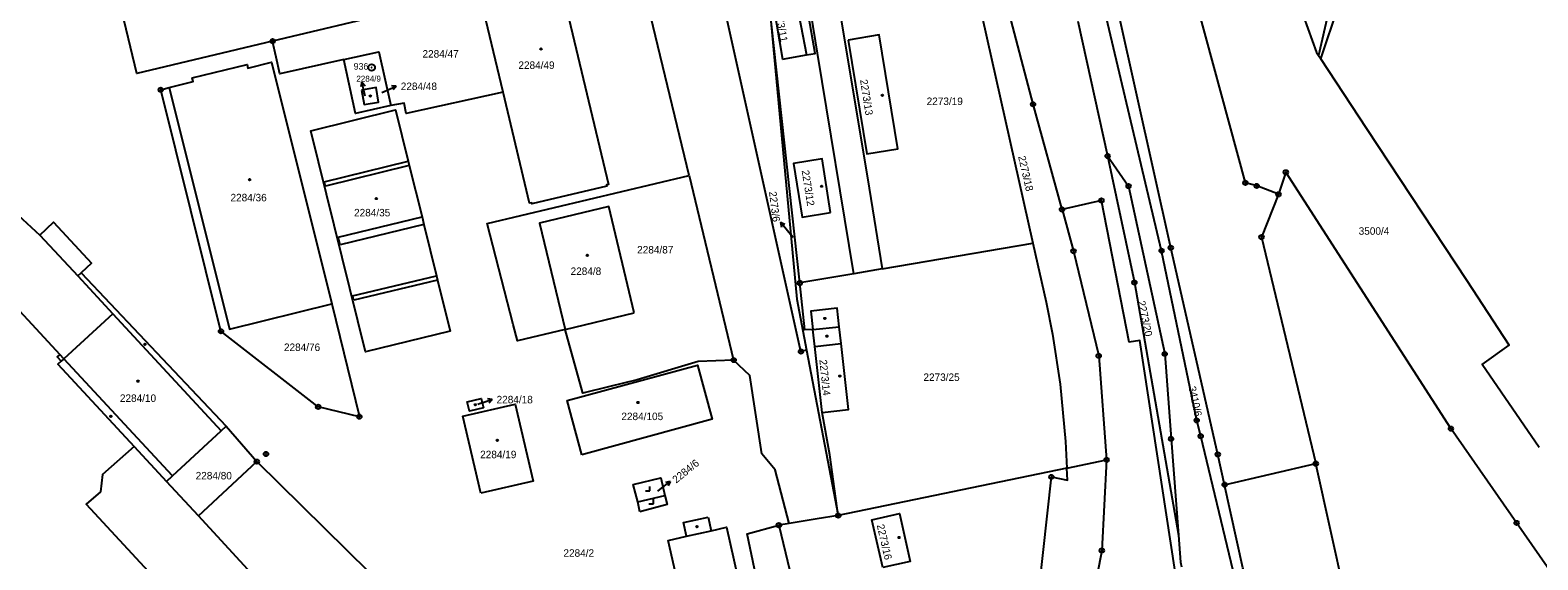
# Model space of a CAD drawing. Extents: x -733394 to -722299, y -1082822 to -1075049.
# Drawn here: x -728924.3 to -728582.2, y -1080231.7 to -1080111.4 of the extents above; entities that cross this region are included whole.
import ezdxf

# ---------------------------------------------------------------- set-up
doc = ezdxf.new("R2010")
doc.units = 0
for name, color, linetype in [('Hranice parcel', 7, 'Continuous'), ('Parcelní čísla', 7, 'Continuous'), ('Pop  PČ popisy', 7, 'Continuous'), ('Vnitřní kresba', 7, 'Continuous'), ('Značky bodu BP', 7, 'Continuous'), ('Značky budov', 7, 'Continuous'), ('Značky kultur', 7, 'Continuous')]:
    doc.layers.add(name, color=color, linetype=linetype)

msp = doc.modelspace()

# ---------------------------------------------------------------- linework, layer by layer
at = {"layer": 'Hranice parcel'}
for p, q in [((-728774.79, -1080144.43), (-728789.19, -1080084.77)), ((-728711.6, -1080093.48), (-728696.79, -1080159.78)), ((-728817.02, -1080125.51), (-728822.46, -1080102.76)), ((-728749.67, -1080168.84), (-728756.71, -1080104.45)), ((-728841.26, -1080107.25), (-728869.31, -1080113.95)), ((-728686.59, -1080109.41), (-728679.82, -1080140.01)), ((-728631.97, -1080117.2), (-728631.45, -1080117.98)), ((-728774.79, -1080144.43), (-728764.68, -1080186.34)), ((-728730.95, -1080165.63), (-728696.79, -1080159.78)), ((-728730.95, -1080165.63), (-728737.42, -1080166.74)), ((-728737.42, -1080166.74), (-728749.67, -1080168.84)), ((-728748.16, -1080184.12), (-728740.95, -1080221.65)), ((-728879.85, -1080201.33), (-728872.89, -1080209.38)), ((-728900.7, -1080205.97), (-728893.37, -1080213.87)), ((-728886.17, -1080221.68), (-728872.89, -1080209.38)), ((-728689.04, -1080210.85), (-728740.95, -1080221.65)), ((-728689.04, -1080210.85), (-728680.04, -1080208.98)), ((-728653.27, -1080214.63), (-728632.56, -1080209.85)), ((-728886.17, -1080221.68), (-728893.37, -1080213.87)), ((-728848.41, -1080262.69), (-728886.17, -1080221.68)), ((-728752.11, -1080223.45), (-728754.43, -1080223.82))]:
    msp.add_line(p, q, dxfattribs=at)
for points in [[(-728737.42, -1080166.74), (-728745.68, -1080116.63), (-728765.96, -1079991.74)], [(-728748.16, -1080184.12), (-728749.41, -1080184.4), (-728775.59, -1080066.46), (-728782.41, -1080049.95), (-728783.38, -1080044.86), (-728786.24, -1080022.54)], [(-728641.02, -1080148.71), (-728645.96, -1080146.81), (-728648.54, -1080146.1), (-728661.28, -1080098.98), (-728659.63, -1080032.24)], [(-728631.45, -1080117.98), (-728627.39, -1080106), (-728622.27, -1080086.64), (-728619.99, -1080056.5), (-728617.8, -1080049.81), (-728606.86, -1080033.11)], [(-728619.68, -1080042.48), (-728623.49, -1080050.29), (-728626.58, -1080093.66), (-728631.97, -1080117.2)], [(-728653.27, -1080214.63), (-728654.79, -1080207.75), (-728665.47, -1080160.84), (-728681.06, -1080090.76), (-728699.52, -1080051.66)], [(-728690.16, -1080152.15), (-728696.72, -1080128.27), (-728707.84, -1080085.86), (-728715.83, -1080054.04)], [(-728630.66, -1080308.05), (-728651.31, -1080234.15), (-728658.68, -1080203.61), (-728659.58, -1080200.04), (-728667.56, -1080161.51), (-728684.06, -1080091.71), (-728696.41, -1080065.56)], [(-728807.03, -1080088.14), (-728793.08, -1080146.46), (-728793.56, -1080146.58), (-728793.5, -1080146.84), (-728810.45, -1080150.87), (-728810.49, -1080150.63), (-728810.98, -1080150.74), (-728817.02, -1080125.51)], [(-728869.31, -1080113.95), (-728900.14, -1080121.31), (-728903.96, -1080105.23), (-728874.06, -1080098.09)], [(-728753.56, -1080118), (-728748.14, -1080117.08), (-728746.17, -1080116.72), (-728748.96, -1080100.62), (-728751.24, -1080100.94), (-728756.35, -1080101.9), (-728753.56, -1080118)], [(-728741.87, -1080099.63), (-728740.52, -1080107.73), (-728733.91, -1080147.32), (-728730.95, -1080165.63)], [(-728756.71, -1080104.45), (-728750.38, -1080172.55), (-728748.16, -1080184.12)], [(-728635.36, -1080108.35), (-728632.43, -1080116.5), (-728631.97, -1080117.2)], [(-728853.13, -1080118.13), (-728867.64, -1080121.39), (-728868.5, -1080117.54), (-728869.31, -1080113.95)], [(-728738.72, -1080113.71), (-728734.49, -1080139.52), (-728727.42, -1080138.36), (-728731.65, -1080112.51), (-728738.72, -1080113.71)], [(-728853.13, -1080118.13), (-728845.22, -1080116.36), (-728842.47, -1080128.52)], [(-728842.47, -1080128.52), (-728850.47, -1080130.33), (-728853.13, -1080118.13)], [(-728581.87, -1080206.22), (-728594.79, -1080187.37), (-728588.7, -1080182.93), (-728598.19, -1080168.32), (-728620.98, -1080133.87), (-728631.45, -1080117.98)], [(-728892.77, -1080124.48), (-728887.35, -1080123.13), (-728887.57, -1080122.26), (-728875.12, -1080119.22), (-728874.91, -1080120.04), (-728869.54, -1080118.71), (-728855.9, -1080173.6)], [(-728855.9, -1080173.6), (-728849.62, -1080199.19), (-728858.97, -1080196.96), (-728881.03, -1080179.79), (-728894.71, -1080124.98), (-728892.77, -1080124.48)], [(-728892.77, -1080124.48), (-728879.09, -1080179.36), (-728855.9, -1080173.6)], [(-728849.12, -1080125.08), (-728848.54, -1080128.34), (-728845.27, -1080127.76), (-728845.83, -1080124.49), (-728849.12, -1080125.08)], [(-728817.02, -1080125.51), (-728838.97, -1080130.35), (-728839.49, -1080127.98), (-728842.47, -1080128.52)], [(-728834.98, -1080155.58), (-728832.11, -1080167.19), (-728831.87, -1080168.17), (-728829.01, -1080179.74), (-728848.2, -1080184.44), (-728860.67, -1080134.27), (-728841.42, -1080129.52), (-728838.53, -1080141.19), (-728838.29, -1080142.19), (-728835.41, -1080153.83), (-728834.98, -1080155.58)], [(-728944.46, -1080135.06), (-728929.01, -1080151.66), (-728922.12, -1080158)], [(-728742.67, -1080152.8), (-728744.6, -1080140.69), (-728751.1, -1080141.74), (-728749.15, -1080153.86), (-728742.67, -1080152.8)], [(-728679.82, -1080140.01), (-728673.74, -1080168.73), (-728663.75, -1080226.11)], [(-728679.82, -1080140.01), (-728675.06, -1080146.83), (-728666.85, -1080184.94), (-728665.41, -1080204.23), (-728663.75, -1080226.11)], [(-728955.63, -1080145.36), (-728940.22, -1080162.17), (-728933.21, -1080168.29), (-728917.64, -1080185.07)], [(-728764.68, -1080186.34), (-728772.77, -1080186.7), (-728786.55, -1080190.85), (-728792.8, -1080192.35), (-728798.9, -1080193.85), (-728802.92, -1080179.37), (-728813.75, -1080181.95), (-728814.69, -1080178.29), (-728820.59, -1080155.33), (-728774.79, -1080144.43)], [(-728553.39, -1080273.16), (-728558.52, -1080265.52), (-728573.03, -1080243.99), (-728574.8, -1080240.8), (-728586.99, -1080223.3), (-728601.9, -1080201.91), (-728639.36, -1080143.69), (-728641.02, -1080148.71)], [(-728641.02, -1080148.71), (-728644.89, -1080158.41), (-728632.56, -1080209.85)], [(-728787.24, -1080175.59), (-728793.04, -1080151.45), (-728808.74, -1080155.25), (-728802.92, -1080179.37), (-728787.24, -1080175.59)], [(-728663.81, -1080237.2), (-728664.51, -1080234.33), (-728672.47, -1080181.92), (-728674.93, -1080182.25), (-728681.21, -1080150.12), (-728690.16, -1080152.15)], [(-728690.16, -1080152.15), (-728687.56, -1080161.6), (-728681.84, -1080185.38), (-728680.04, -1080208.98)], [(-728922.12, -1080158), (-728919.02, -1080155.05), (-728910.41, -1080164.35), (-728912.73, -1080166.5), (-728879.85, -1080201.33)], [(-728922.12, -1080158), (-728913.54, -1080167.25), (-728905.59, -1080175.83), (-728916.71, -1080186.06), (-728917.64, -1080185.07)], [(-728696.79, -1080159.78), (-728693.78, -1080173.23), (-728692.29, -1080180.44), (-728690.56, -1080191.84), (-728689.37, -1080204.79), (-728689.04, -1080210.85)], [(-728746.7, -1080179.43), (-728748.5, -1080179.49), (-728749.67, -1080168.84)], [(-728744.62, -1080198.22), (-728738.62, -1080197.56), (-728740.28, -1080182.59), (-728740.71, -1080178.77), (-728741.17, -1080174.56), (-728747.17, -1080175.22), (-728746.7, -1080179.43)], [(-728744.62, -1080198.22), (-728746.28, -1080183.25), (-728746.7, -1080179.43)], [(-728917.64, -1080185.07), (-728918.23, -1080185.61), (-728917.31, -1080186.6), (-728918.04, -1080187.29), (-728900.7, -1080205.97)], [(-728752.11, -1080223.45), (-728755.25, -1080211.25), (-728758.32, -1080207.61), (-728761, -1080189.81), (-728764.68, -1080186.34)], [(-728799.14, -1080207.84), (-728802.49, -1080195.51), (-728772.88, -1080187.48), (-728769.55, -1080199.75), (-728799.14, -1080207.84)], [(-728822.08, -1080216.58), (-728826.14, -1080199.04), (-728814.26, -1080196.34), (-728810.17, -1080213.83), (-728822.08, -1080216.58)], [(-728821.45, -1080197.21), (-728824.63, -1080197.95), (-728825.13, -1080195.79), (-728821.95, -1080195.06), (-728821.45, -1080197.21)], [(-728740.95, -1080221.65), (-728742.88, -1080207.86), (-728744.62, -1080198.22)], [(-728893.37, -1080213.87), (-728892.05, -1080212.64), (-728880.97, -1080202.37), (-728879.85, -1080201.33)], [(-728900.7, -1080205.97), (-728907.9, -1080212.32), (-728908.37, -1080216.28), (-728911.61, -1080219.04), (-728863.64, -1080270.92), (-728866.08, -1080273.13), (-728868.18, -1080273.17)], [(-728872.89, -1080209.38), (-728837.18, -1080244.57), (-728832.81, -1080248.41)], [(-728728.7, -1080396.49), (-728712.16, -1080321.77), (-728703.02, -1080284.2), (-728696.32, -1080247.23), (-728692.56, -1080212.86), (-728688.89, -1080213.62), (-728689.04, -1080210.85)], [(-728680.04, -1080208.98), (-728681.12, -1080229.58), (-728684.34, -1080246.5), (-728693.5, -1080292.91), (-728701.3, -1080331.89), (-728714.47, -1080392.88), (-728727.79, -1080444.04)], [(-728606.47, -1080327.62), (-728632.47, -1080210.23), (-728632.56, -1080209.85)], [(-728785.94, -1080220.76), (-728786.46, -1080218.55), (-728787.45, -1080214.55), (-728781.23, -1080213.11), (-728780.28, -1080217.07), (-728779.74, -1080219.13), (-728785.94, -1080220.76)], [(-728628.39, -1080307.72), (-728649.09, -1080233.53), (-728653.27, -1080214.63)], [(-728730.86, -1080233.44), (-728733.31, -1080222.6), (-728727.04, -1080221.19), (-728724.63, -1080232.03), (-728730.86, -1080233.44)], [(-728770.47, -1080221.98), (-728769.79, -1080225.08), (-728766.27, -1080224.28), (-728758.94, -1080256.97), (-728772.15, -1080259.96), (-728774.42, -1080249.88), (-728775.84, -1080243.58), (-728779.52, -1080227.27), (-728775.4, -1080226.34), (-728776.1, -1080223.25), (-728770.47, -1080221.98)], [(-728755.99, -1080252.53), (-728761.65, -1080225.76), (-728754.43, -1080223.82)], [(-728754.43, -1080223.82), (-728747.91, -1080250.82), (-728755.99, -1080252.53)], [(-728740.95, -1080221.65), (-728745.69, -1080222.41), (-728752.11, -1080223.45)], [(-728663.75, -1080226.11), (-728663.29, -1080232.22), (-728663.02, -1080233.3)]]:
    msp.add_lwpolyline(points, dxfattribs=at)
at = {"layer": 'Pop  PČ popisy'}
for p, q in [((-728849.05, -1080123.22), (-728849.31, -1080124.3)), ((-728848.37, -1080126.14), (-728849.05, -1080123.22)), ((-728849.05, -1080123.22), (-728848.33, -1080124.08)), ((-728844.55, -1080125.57), (-728844, -1080125.34)), ((-728844, -1080125.34), (-728841.24, -1080124.17)), ((-728841.24, -1080124.17), (-728842.35, -1080124.1)), ((-728841.24, -1080124.17), (-728841.96, -1080125.02)), ((-728848.3, -1080126.44), (-728848.37, -1080126.14)), ((-728752.13, -1080157.36), (-728754.06, -1080155.06)), ((-728754.06, -1080155.06), (-728753.03, -1080155.51)), ((-728754.06, -1080155.06), (-728753.8, -1080156.15)), ((-728751.16, -1080158.52), (-728752.13, -1080157.36)), ((-728822.76, -1080196.37), (-728822.33, -1080196.23)), ((-728822.33, -1080196.23), (-728819.48, -1080195.3)), ((-728819.48, -1080195.3), (-728820.58, -1080195.14)), ((-728819.48, -1080195.3), (-728820.27, -1080196.09)), ((-728781.45, -1080215.75), (-728779.09, -1080213.9)), ((-728779.09, -1080213.9), (-728780.18, -1080214.12)), ((-728779.09, -1080213.9), (-728779.57, -1080214.91)), ((-728781.9, -1080216.1), (-728781.45, -1080215.75))]:
    msp.add_line(p, q, dxfattribs=at)
at = {"layer": 'Vnitřní kresba'}
for p, q in [((-728751.24, -1080100.94), (-728748.14, -1080117.08)), ((-728857.59, -1080145.84), (-728838.53, -1080141.19)), ((-728838.29, -1080142.19), (-728857.34, -1080146.84)), ((-728857.34, -1080146.84), (-728857.59, -1080145.84)), ((-728854.46, -1080158.44), (-728835.41, -1080153.83)), ((-728834.98, -1080155.58), (-728854.02, -1080160.18)), ((-728854.02, -1080160.18), (-728854.46, -1080158.44)), ((-728913.54, -1080167.25), (-728912.73, -1080166.5)), ((-728851.15, -1080171.75), (-728832.11, -1080167.19)), ((-728831.87, -1080168.17), (-728850.91, -1080172.72)), ((-728850.91, -1080172.72), (-728851.15, -1080171.75)), ((-728905.59, -1080175.83), (-728880.97, -1080202.37)), ((-728746.7, -1080179.43), (-728740.71, -1080178.77)), ((-728746.28, -1080183.25), (-728740.28, -1080182.59)), ((-728916.71, -1080186.06), (-728917.31, -1080186.6)), ((-728892.05, -1080212.64), (-728916.71, -1080186.06)), ((-728786.46, -1080218.55), (-728780.28, -1080217.07)), ((-728775.4, -1080226.34), (-728769.79, -1080225.08))]:
    msp.add_line(p, q, dxfattribs=at)
at = {"layer": 'Značky bodu BP'}
for centre, radius in [((-728869.31, -1080113.95), 0.5), ((-728869.31, -1080113.95), 0.0303), ((-728846.83, -1080119.92), 0.75), ((-728846.83, -1080119.92), 0.03), ((-728894.71, -1080124.98), 0.5), ((-728894.71, -1080124.98), 0.0303), ((-728696.72, -1080128.27), 0.5), ((-728696.72, -1080128.27), 0.0303), ((-728679.82, -1080140.01), 0.5), ((-728679.82, -1080140.01), 0.0303), ((-728648.54, -1080146.1), 0.5), ((-728648.54, -1080146.1), 0.0303), ((-728639.36, -1080143.69), 0.5), ((-728639.36, -1080143.69), 0.0303), ((-728675.06, -1080146.83), 0.5), ((-728675.06, -1080146.83), 0.0303), ((-728645.96, -1080146.81), 0.5), ((-728645.96, -1080146.81), 0.0303), ((-728641.02, -1080148.71), 0.5), ((-728641.02, -1080148.71), 0.0303), ((-728690.16, -1080152.15), 0.5), ((-728690.16, -1080152.15), 0.0303), ((-728681.21, -1080150.12), 0.5), ((-728681.21, -1080150.12), 0.0303), ((-728644.89, -1080158.41), 0.5), ((-728644.89, -1080158.41), 0.0303), ((-728687.56, -1080161.6), 0.5), ((-728687.56, -1080161.6), 0.0303), ((-728667.56, -1080161.51), 0.5), ((-728667.56, -1080161.51), 0.0303), ((-728665.47, -1080160.84), 0.5), ((-728665.47, -1080160.84), 0.0303), ((-728749.67, -1080168.84), 0.5), ((-728749.67, -1080168.84), 0.0303), ((-728673.74, -1080168.73), 0.5), ((-728673.74, -1080168.73), 0.0303), ((-728881.03, -1080179.79), 0.5), ((-728881.03, -1080179.79), 0.0303), ((-728764.68, -1080186.34), 0.5), ((-728764.68, -1080186.34), 0.0303), ((-728749.41, -1080184.4), 0.5), ((-728749.41, -1080184.4), 0.0303), ((-728681.84, -1080185.38), 0.5), ((-728681.84, -1080185.38), 0.0303), ((-728666.85, -1080184.94), 0.5), ((-728666.85, -1080184.94), 0.0303), ((-728858.97, -1080196.96), 0.5), ((-728858.97, -1080196.96), 0.0303), ((-728849.62, -1080199.19), 0.5), ((-728849.62, -1080199.19), 0.0303), ((-728659.58, -1080200.04), 0.5), ((-728659.58, -1080200.04), 0.0303), ((-728665.41, -1080204.23), 0.5), ((-728665.41, -1080204.23), 0.0303), ((-728658.68, -1080203.61), 0.5), ((-728658.68, -1080203.61), 0.0303), ((-728601.9, -1080201.91), 0.5), ((-728601.9, -1080201.91), 0.0303), ((-728870.82, -1080207.66), 0.5), ((-728870.82, -1080207.66), 0.0303), ((-728654.79, -1080207.75), 0.5), ((-728872.89, -1080209.38), 0.5), ((-728872.89, -1080209.38), 0.0303), ((-728680.04, -1080208.98), 0.5), ((-728680.04, -1080208.98), 0.0303), ((-728654.79, -1080207.75), 0.0303), ((-728632.56, -1080209.85), 0.5), ((-728632.56, -1080209.85), 0.0303), ((-728692.56, -1080212.86), 0.5), ((-728692.56, -1080212.86), 0.0303), ((-728653.27, -1080214.63), 0.5), ((-728653.27, -1080214.63), 0.0303), ((-728740.95, -1080221.65), 0.5), ((-728754.43, -1080223.82), 0.5), ((-728754.43, -1080223.82), 0.0303), ((-728740.95, -1080221.65), 0.0303), ((-728586.99, -1080223.3), 0.5), ((-728586.99, -1080223.3), 0.0303), ((-728681.12, -1080229.58), 0.5), ((-728681.12, -1080229.58), 0.0303)]:
    msp.add_circle(centre, radius, dxfattribs=at)
at = {"layer": 'Značky budov'}
for centre in [(-728808.4, -1080115.7), (-728847.12, -1080126.41), (-728730.93, -1080126.26), (-728874.53, -1080145.38), (-728744.69, -1080146.87), (-728845.78, -1080149.67), (-728797.89, -1080162.56), (-728743.98, -1080176.89), (-728898.28, -1080182.78), (-728743.52, -1080180.92), (-728740.58, -1080189.98), (-728899.86, -1080191.12), (-728823.32, -1080196.49), (-728786.41, -1080195.98), (-728906.02, -1080199.11), (-728818.32, -1080204.57), (-728773.01, -1080224.18), (-728727.13, -1080226.61)]:
    msp.add_circle(centre, 0.175, dxfattribs=at)
at = {"layer": 'Značky kultur'}
for p, q in [((-728784.69, -1080216.01), (-728783.69, -1080216.01)), ((-728783.69, -1080216.01), (-728783.69, -1080215.01)), ((-728783.9, -1080218.94), (-728782.9, -1080218.94)), ((-728782.9, -1080218.94), (-728782.9, -1080217.94))]:
    msp.add_line(p, q, dxfattribs=at)

# ---------------------------------------------------------------- texts
at = {"layer": 'Parcelní čísla'}
for s, rotation, p in [('2273/11', 280, (-728755.47, -1080106.16)), ('2273/13', 279, (-728736, -1080122.77)), ('2273/18', 283, (-728700.13, -1080140.16)), ('2273/12', 279, (-728749.25, -1080143.35)), ('2273/6', 277, (-728756.66, -1080148.15)), ('2273/20', 282, (-728672.98, -1080173.07)), ('2273/14', 276, (-728745.23, -1080186.31)), ('3410/6', 282, (-728661.47, -1080192.48)), ('2284/6', 39, (-728777.74, -1080214.41)), ('2273/16', 283, (-728732.21, -1080223.82))]:
    msp.add_text(s, height=1.7, rotation=rotation, dxfattribs=at).set_placement(p)
for s, height, p in [('2284/47', 1.7, (-728835.3, -1080117.68)), ('2284/49', 1.7, (-728813.53, -1080120.24)), ('2284/9', 1.36, (-728850.3, -1080123.14)), ('2284/48', 1.7, (-728840.23, -1080125.04)), ('2273/19', 1.7, (-728720.88, -1080128.44)), ('2284/36', 1.7, (-728878.87, -1080150.3)), ('2284/35', 1.7, (-728850.83, -1080153.72)), ('3500/4', 1.7, (-728622.83, -1080157.89)), ('2284/87', 1.7, (-728786.58, -1080162.14)), ('2284/8', 1.7, (-728801.69, -1080167.02)), ('2284/76', 1.7, (-728866.74, -1080184.28)), ('2273/25', 1.7, (-728721.61, -1080191.08)), ('2284/10', 1.7, (-728903.97, -1080195.84)), ('2284/18', 1.7, (-728818.48, -1080196.16)), ('2284/105', 1.7, (-728790.16, -1080199.97)), ('2284/19', 1.7, (-728822.21, -1080208.62)), ('2284/80', 1.7, (-728886.78, -1080213.43)), ('2284/2', 1.7, (-728803.31, -1080230.99))]:
    msp.add_text(s, height=height, dxfattribs=at).set_placement(p)
at = {"layer": 'Značky bodu BP'}
msp.add_text('936', height=1.5, dxfattribs=at).set_placement((-728850.93, -1080120.42))

doc.saveas('drawing.dxf')
